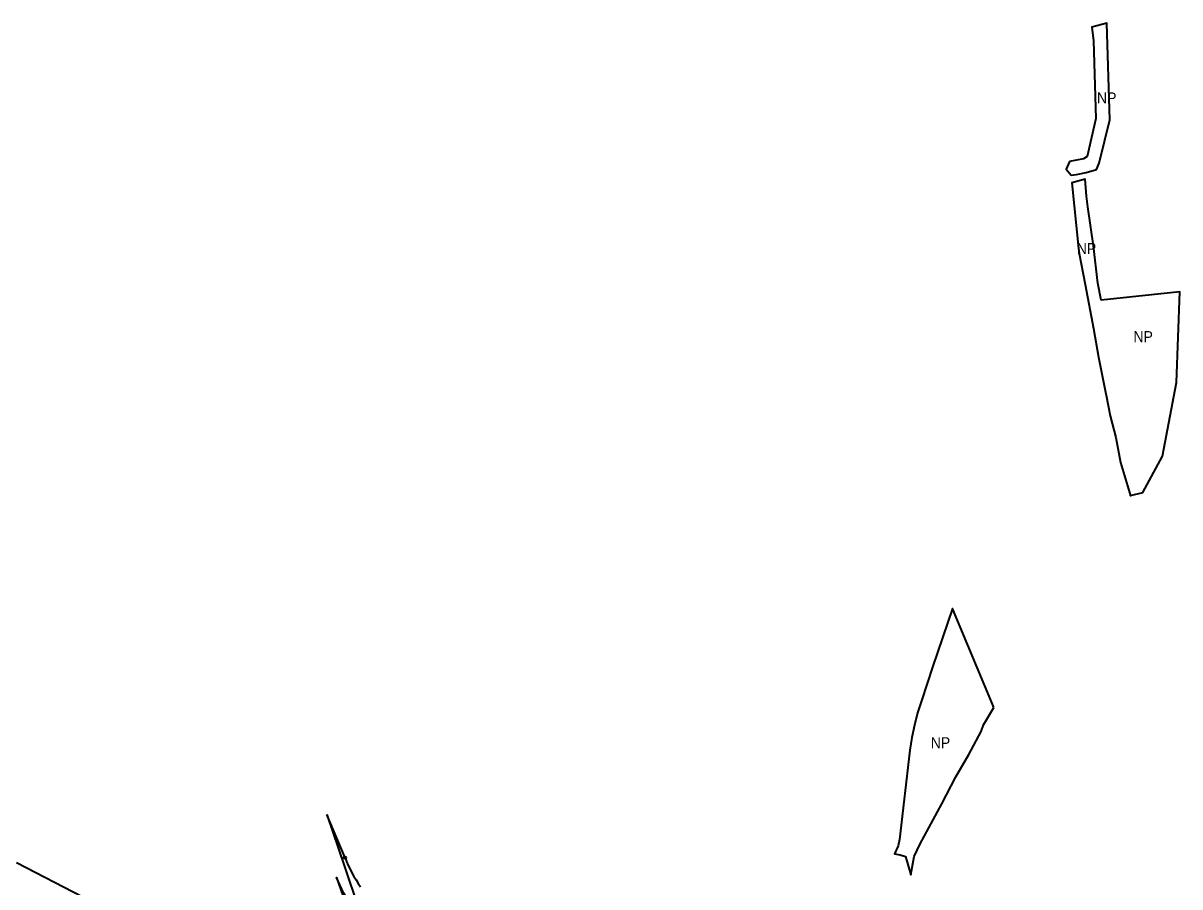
# Model space of a CAD drawing. Extents: x -650276 to -642489, y -1074311 to -1066658.
# Drawn here: x -646929 to -645670, y -1068433 to -1067493 of the extents above; entities that cross this region are included whole.
import ezdxf

# ---------------------------------------------------------------- set-up
doc = ezdxf.new("R2010")
doc.units = 0
doc.header["$LTSCALE"] = 4.8
doc.header["$PDMODE"] = 32
doc.header["$PDSIZE"] = 2.4
for name, color, linetype, lineweight in [('24', 7, 'Continuous', 35), ('42', 7, 'Continuous', 35), ('48', 7, 'Continuous', 35)]:
    doc.layers.add(name, color=color, linetype=linetype, lineweight=lineweight)
doc.layers.add('62', color=7, linetype='Continuous')
doc.layers.add('63', color=7, linetype='Continuous')

msp = doc.modelspace()

# ---------------------------------------------------------------- linework, layer by layer
at = {"layer": '24'}
msp.add_line((-646578.881, -1068401.54), (-646598.635, -1068354.436), dxfattribs=at)
msp.add_line((-646578.881, -1068401.54), (-646598.635, -1068354.436), dxfattribs=at)
for points in [[(-646598.635, -1068354.436), (-646579.62, -1068411.29), (-646564.78, -1068455.41), (-646561.544, -1068464.842)], [(-646598.635, -1068354.436), (-646579.62, -1068411.29), (-646564.78, -1068455.41), (-646561.544, -1068464.842)], [(-646864.48, -1068444.64), (-646936.47, -1068407.23)]]:
    msp.add_lwpolyline(points, dxfattribs=at)
for start in [200.6496, 200.64975]:
    msp.add_arc((-646447.332, -1068351.964), 140.58, start, 215.36619, dxfattribs=at)
msp.add_point((-646578.881, -1068401.54), dxfattribs=at)
at = {"layer": '42'}
msp.add_lwpolyline([(-646561.544, -1068464.842), (-646572.984, -1068451.81), (-646580.625, -1068439.803), (-646588.07, -1068422.96), (-646576.4, -1068457.27), (-646568.87, -1068479.14), (-646556.22, -1068515.84), (-646545.57, -1068511.42), (-646537.71, -1068508.16)], dxfattribs=at)
at = {"layer": '48'}
for points in [[(-645757.79, -1067645.206), (-645746.448, -1067597.944), (-645749.67, -1067492.54), (-645765.859, -1067496.872), (-645764.084, -1067511.925), (-645761.499, -1067596.501), (-645770.809, -1067637.786), (-645775.114, -1067640.43), (-645790.381, -1067643.17)], [(-645790.381, -1067643.17), (-645793.94, -1067651.61), (-645788.395, -1067658.038), (-645782.72, -1067657.28), (-645772.13, -1067655.13), (-645760.67, -1067652.05), (-645757.79, -1067645.206)], [(-645872.64, -1068238.08), (-645874.15, -1068234.44), (-645917.44, -1068129.99), (-645938.87, -1068193.06)], [(-645938.87, -1068193.06), (-645951.35, -1068230.61), (-645955.63, -1068243.79), (-645959.15, -1068257.17), (-645961.93, -1068270.74), (-645963.94, -1068284.44), (-645975.46, -1068381.74), (-645976.72, -1068388.53), (-645980.61, -1068397.35), (-645974.67, -1068398.28), (-645968.86, -1068400.15), (-645962.86, -1068420.15), (-645959.41, -1068400.16), (-645952.92, -1068386.53), (-645929.29, -1068342.91), (-645914.12, -1068313.54), (-645899.73, -1068289.25), (-645886.28, -1068264.22), (-645883.87, -1068256.88), (-645872.64, -1068238.08)]]:
    msp.add_lwpolyline(points, dxfattribs=at)
msp.add_lwpolyline([(-645750.41, -1067897.81), (-645745.86, -1067920.32), (-645739.85, -1067943.75), (-645734.61, -1067971.28), (-645723.73, -1068007.49), (-645723.785, -1068007.069), (-645710.519, -1068003.601), (-645688.88, -1067964.087), (-645673.827, -1067884.119), (-645670.064, -1067785.335), (-645755.758, -1067794.254), (-645759.32, -1067775.89), (-645763.92, -1067735.14), (-645770.39, -1067692.63), (-645771.86, -1067680.92), (-645773.23, -1067662.67), (-645787.55, -1067666.46), (-645780.39, -1067737.84), (-645779.64, -1067743.41), (-645773.04, -1067777.35), (-645764.11, -1067825.26), (-645758.47, -1067856.55), (-645751.08, -1067894.5)], close=True, dxfattribs=at)

# ---------------------------------------------------------------- texts
at = {"layer": '62', "width": 0.95}
for p in [(-645782.298, -1067744), (-645720.583, -1067840.041), (-645941.298, -1068282.326)]:
    msp.add_text('NP', height=12, dxfattribs=at).set_placement(p)
at = {"layer": '63', "width": 0.95}
msp.add_text('NP', height=12, dxfattribs=at).set_placement((-645760.298, -1067580))

doc.saveas('drawing.dxf')
